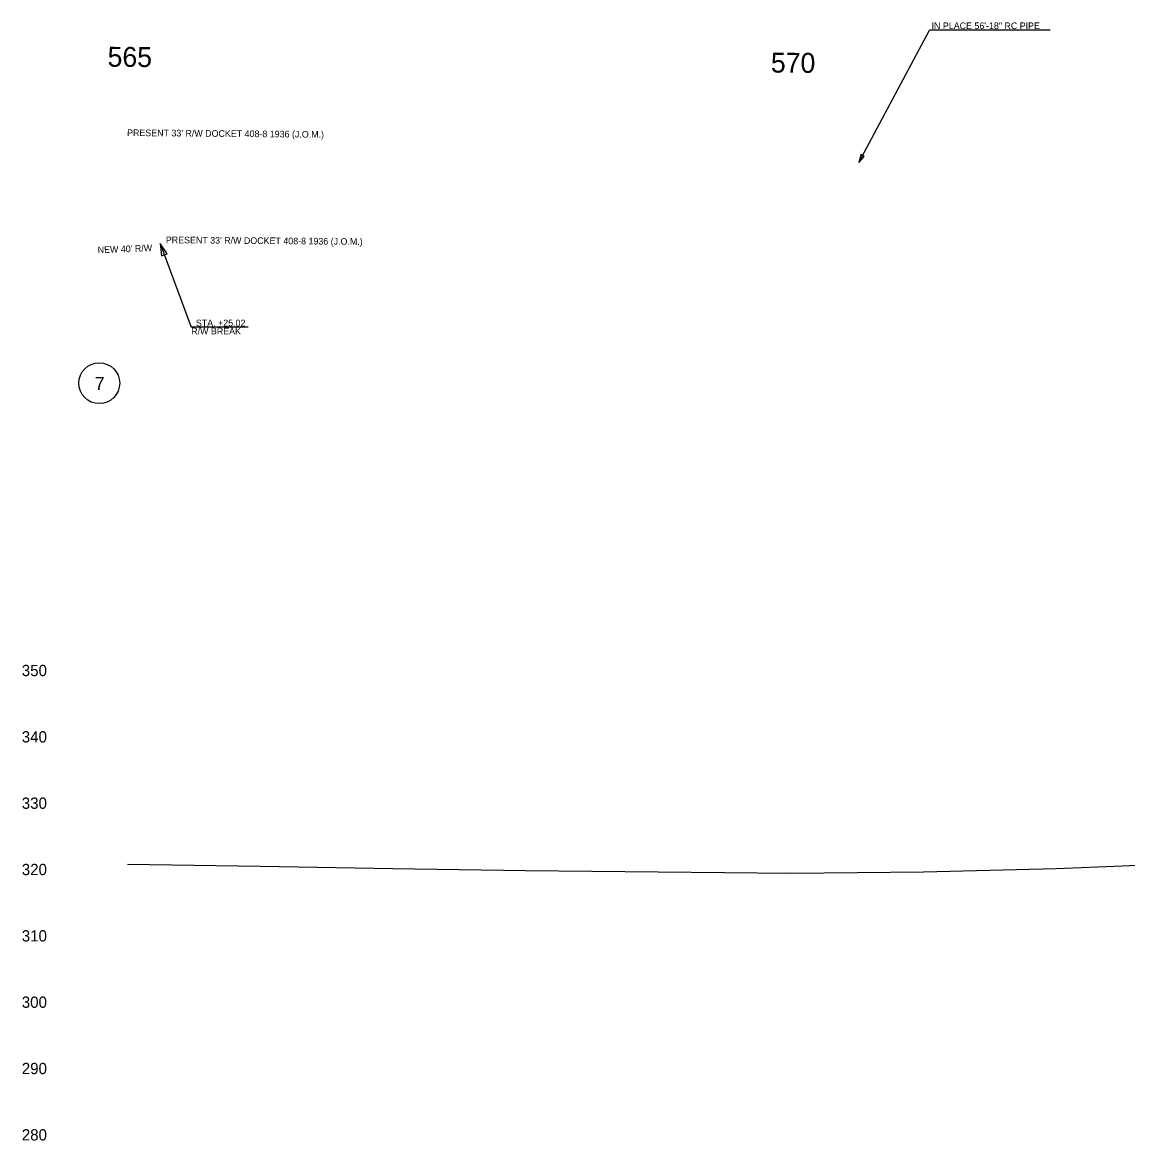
# Model space of a CAD drawing. Extents: x 48556 to 51363, y 45290 to 53458.
# Drawn here: x 49109 to 49942, y 52475 to 53318 of the extents above; entities that cross this region are included whole.
import ezdxf

# ---------------------------------------------------------------- set-up
doc = ezdxf.new("R2010")
doc.units = 0
for name, color, linetype in [('Level 1', 7, 'Continuous'), ('Level 12', 7, 'Continuous'), ('Level 19', 7, 'Continuous'), ('Level 24', 7, 'Continuous'), ('Level 33', 7, 'Continuous'), ('Level 40', 7, 'Continuous'), ('Level 42', 7, 'Continuous'), ('Level 6', 7, 'Continuous')]:
    doc.layers.add(name, color=color, linetype=linetype)

msp = doc.modelspace()

# ---------------------------------------------------------------- linework, layer by layer
at = {"layer": 'Level 12'}
msp.add_circle((49166.56, 53046.16), 15.42, dxfattribs=at)
at = {"layer": 'Level 24'}
for p, q in [((49740.5, 53218.46), (49739, 53212.46)), ((49739, 53212.46), (49743.15, 53217.05)), ((49743.15, 53217.05), (49740.5, 53218.46)), ((49212.58, 53151.38), (49213.58, 53142.16)), ((49217.81, 53143.72), (49212.58, 53151.38)), ((49213.58, 53142.16), (49217.81, 53143.72))]:
    msp.add_line(p, q, dxfattribs=at)
at = {"layer": 'Level 33'}
for p in [(49212.58, 53151.38), (49278.84, 53088.5)]:
    msp.add_line(p, (49235.81, 53088.5), dxfattribs=at)
at = {"layer": 'Level 40'}
msp.add_lwpolyline([(49187.91, 52683.7), (49237.91, 52682.88), (49287.91, 52682.05), (49387.93, 52680.45), (49437.91, 52679.63), (49487.91, 52678.8), (49537.91, 52678.38), (49587.9, 52677.95), (49687.94, 52676.75), (49737.91, 52677.27), (49787.91, 52677.8), (49837.91, 52679.1), (49887.91, 52680.4), (49937.91, 52682.47), (49987.91, 52684.55)], dxfattribs=at)
at = {"layer": 'Level 6'}
for p in [(49739, 53212.46), (49883.25, 53312.2)]:
    msp.add_line(p, (49792.32, 53312.2), dxfattribs=at)

# ---------------------------------------------------------------- texts
at = {"layer": 'Level 1'}
for p in [(49187.53, 53232.48), (49216.72, 53151.71)]:
    msp.add_text("PRESENT 33' R/W DOCKET 408-8 1936 (J.O.M.)", height=5, rotation=359.49443, dxfattribs=at).set_placement(p)
at = {"layer": 'Level 12'}
msp.add_text('7', height=10, dxfattribs=at).set_placement((49163.14, 53040.92))
at = {"layer": 'Level 19'}
for s, p in [('565', (49172.8, 53284.74)), ('570', (49672.75, 53280.33))]:
    msp.add_text(s, height=15, rotation=359.49443, dxfattribs=at).set_placement(p)
at = {"layer": 'Level 33'}
msp.add_text("NEW 40' R/W", height=5, rotation=2.08957, dxfattribs=at).set_placement((49165.48, 53144.11))
for s, p in [('R/W BREAK', (49235.88, 53082.93)), ('STA. +25.02', (49239.4, 53089.05))]:
    msp.add_text(s, height=5, dxfattribs=at).set_placement(p)
at = {"layer": 'Level 42'}
for s, p in [('350', (49108.18, 52825.35)), ('340', (49108.18, 52775.35)), ('330', (49108.18, 52725.35)), ('320', (49108.18, 52675.35)), ('310', (49108.18, 52625.35)), ('300', (49108.18, 52575.35)), ('290', (49108.18, 52525.35)), ('280', (49108.18, 52475.35))]:
    msp.add_text(s, height=8.5, dxfattribs=at).set_placement(p)
at = {"layer": 'Level 6'}
msp.add_text('IN PLACE 56\'-18" RC PIPE', height=5, dxfattribs=at).set_placement((49793.88, 53313.06))

doc.saveas('drawing.dxf')
